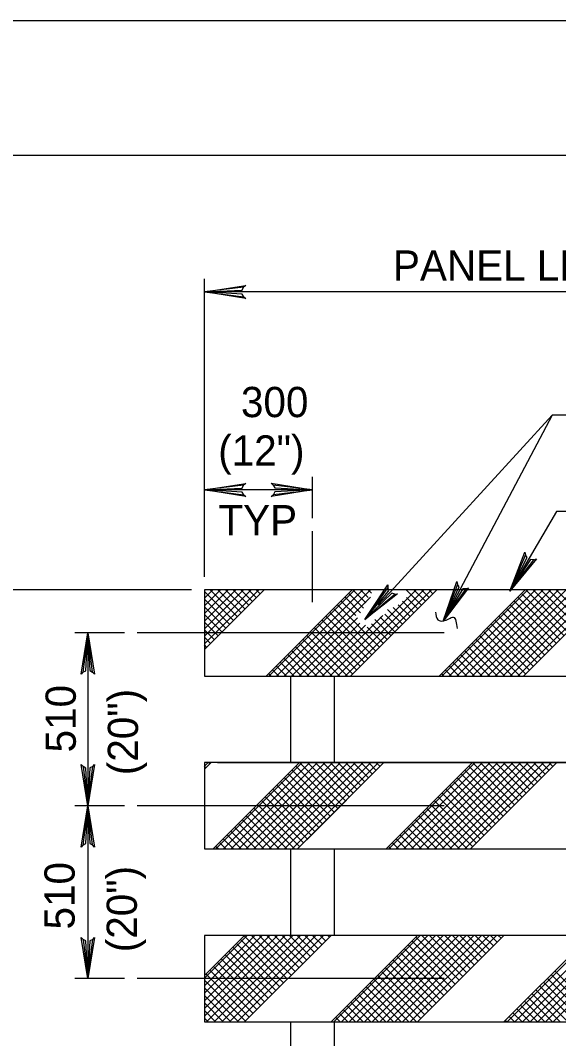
# Model space of a CAD drawing. Extents: x -4 to 901, y -468 to 720.
# Drawn here: x 119.8 to 179.6, y 606.9 to 720 of the extents above; entities that cross this region are included whole.
import ezdxf

# ---------------------------------------------------------------- set-up
doc = ezdxf.new("R2010")
doc.units = 0
for name, color, linetype in [('1', 7, 'Continuous'), ('2', 7, 'Continuous'), ('3', 7, 'Continuous'), ('PLT-BNDY', 7, 'Continuous')]:
    doc.layers.add(name, color=color, linetype=linetype)

msp = doc.modelspace()

# ---------------------------------------------------------------- linework, layer by layer
at = {"layer": '1'}
msp.add_lwpolyline([(822.258, 141.027875), (822.258, 705.027875), (36.258, 705.027875), (36.258, 141.027875), (822.258, 141.027875), (822.258, 167.386875), (622.258, 167.386875), (622.258, 232.064375), (822.258, 232.064375), (822.258, 261.027875), (622.258, 261.027875), (622.258, 141.027875), (701.0595, 141.027875), (701.0595, 167.386875), (701.0595, 141.027875), (778.0595, 141.027875), (778.0595, 167.386875), (778.0595, 155.070375), (822.258, 155.070375)], dxfattribs=at)
at = {"layer": '2'}
for p, q in [((140.2805, 658.235125), (140.2805, 691.305125)), ((284.2805, 689.865125), (140.2805, 689.865125)), ((152.2805, 664.733125), (152.2805, 669.313125)), ((152.2805, 667.873125), (140.2805, 667.873125)), ((152.2805, 655.413125), (152.2805, 663.293125)), ((138.8405, 656.795125), (93.0485, 656.795125)), ((140.2805, 650.161125), (146.9145, 656.795125)), ((147.14125, 647.205125), (156.74125, 656.805125)), ((156.5145, 647.195125), (166.1145, 656.795125)), ((166.34125, 647.205125), (175.94125, 656.805125)), ((175.7145, 647.195125), (185.3145, 656.795125)), ((131.3825, 651.995125), (125.8845, 651.995125)), ((127.3245, 651.995125), (127.3245, 632.795125)), ((166.9105, 651.995125), (132.8225, 651.995125)), ((140.2805, 636.847125), (141.0285, 637.595125)), ((141.25525, 628.005125), (150.85525, 637.605125)), ((141.7205, 637.595125), (192.7225, 637.595125)), ((150.6285, 627.995125), (160.2285, 637.595125)), ((160.45525, 628.005125), (170.05525, 637.605125)), ((169.8285, 627.995125), (179.4285, 637.595125)), ((151.6465, 629.013125), (156.0525, 633.419125)), ((131.3825, 632.795125), (125.8845, 632.795125)), ((127.3245, 632.795125), (127.3245, 613.595125)), ((166.9105, 632.795125), (132.8225, 632.795125)), ((140.2805, 613.933125), (144.7425, 618.395125)), ((144.7425, 608.795125), (154.3425, 618.395125)), ((154.3425, 608.795125), (163.9425, 618.395125)), ((163.9425, 608.795125), (173.5425, 618.395125)), ((173.5425, 608.795125), (183.1425, 618.395125)), ((131.3825, 613.595125), (125.8845, 613.595125)), ((166.9105, 613.595125), (132.8225, 613.595125))]:
    msp.add_line(p, q, dxfattribs=at)
for points in [[(144.6405, 689.317125), (144.4765, 689.633125), (140.2805, 689.865125), (144.6405, 689.317125), (144.8625, 689.127125), (140.2805, 689.865125), (144.4745, 690.073125), (144.6265, 690.385125), (140.2805, 689.865125), (144.8625, 690.593125), (144.6265, 690.385125)], [(178.9225, 676.169125), (160.9405, 656.573125)], [(183.7225, 676.169125), (178.9225, 676.169125), (166.9905, 653.625125)], [(144.6405, 667.327125), (144.4765, 667.643125), (140.2805, 667.873125), (144.6405, 667.327125), (144.8625, 667.135125), (140.2805, 667.873125), (144.4745, 668.081125), (144.6265, 668.393125), (140.2805, 667.873125), (144.8625, 668.603125), (144.6265, 668.393125)], [(147.9205, 668.421125), (148.0845, 668.105125), (152.2805, 667.873125), (147.9205, 668.421125), (147.6985, 668.613125), (152.2805, 667.873125), (148.0865, 667.667125), (147.9345, 667.355125), (152.2805, 667.873125), (147.6985, 667.145125), (147.9345, 667.355125)], [(184.1885, 665.477125), (179.3885, 665.477125), (174.1945, 656.647125)], [(176.8765, 660.127125), (176.5225, 660.147125), (174.1945, 656.647125), (176.8765, 660.127125), (177.1545, 660.223125), (174.1945, 656.647125), (176.1425, 660.367125), (175.9505, 660.657125), (174.1945, 656.647125), (175.8905, 660.965125), (175.9505, 660.657125)], [(160.2105, 656.669125), (160.6505, 657.333125), (160.6445, 657.019125)], [(169.3385, 656.893125), (168.9845, 656.897125), (166.8165, 653.297125), (169.3385, 656.893125), (169.6125, 657.001125), (166.8165, 653.297125), (168.5945, 657.099125), (168.3905, 657.381125), (166.8165, 653.297125), (168.3165, 657.687125), (168.3905, 657.381125)], [(140.2805, 655.856375), (141.21925, 656.795125)], [(140.2805, 655.007875), (142.06775, 656.795125)], [(140.2805, 654.159375), (142.91625, 656.795125)], [(140.2805, 653.310875), (143.76475, 656.795125)], [(140.2805, 652.462375), (144.61325, 656.795125)], [(140.2805, 651.613875), (145.46175, 656.795125)], [(140.2805, 650.765375), (146.31025, 656.795125)], [(143.49725, 653.377875), (140.2805, 656.594625)], [(143.9215, 653.802125), (140.9285, 656.795125)], [(144.34575, 654.226375), (141.777, 656.795125)], [(144.77, 654.650625), (142.6255, 656.795125)], [(145.19425, 655.074875), (143.474, 656.795125)], [(145.6185, 655.499125), (144.3225, 656.795125)], [(146.04275, 655.923375), (145.171, 656.795125)], [(146.467, 656.347625), (146.0195, 656.795125)], [(147.43525, 647.205125), (157.03525, 656.805125)], [(148.27375, 647.195125), (157.87375, 656.795125)], [(149.12225, 647.195125), (158.72225, 656.795125)], [(154.21325, 647.195125), (163.81325, 656.795125)], [(155.06225, 647.195125), (164.66225, 656.795125)], [(157.61375, 654.237625), (155.89725, 655.961125)], [(155.91075, 647.195125), (165.51075, 656.795125)], [(157.95825, 654.742375), (156.3215, 656.385375)], [(158.22325, 655.326375), (156.74575, 656.809625)], [(158.4725, 655.926625), (157.60725, 656.795125)], [(158.83275, 656.414875), (158.454, 656.795125)], [(159.5005, 655.597125), (159.8345, 656.101125)], [(159.9845, 656.101125), (159.5245, 655.461125)], [(159.8345, 656.101125), (160.2105, 656.669125)], [(160.3765, 656.647125), (159.9845, 656.101125)], [(160.1425, 655.939125), (160.6965, 656.605125)], [(160.9405, 656.573125), (160.1425, 655.705125)], [(161.4385, 656.307125), (161.0965, 656.401125), (160.1425, 655.471125)], [(160.1425, 655.207125), (161.4385, 656.307125), (161.7305, 656.341125), (160.1425, 655.089125)], [(160.6965, 656.605125), (160.7705, 656.695125), (160.6445, 657.019125), (160.3765, 656.647125)], [(164.39575, 655.081375), (162.6885, 656.795125)], [(164.82075, 655.504625), (163.53525, 656.795125)], [(165.246, 655.928125), (164.38225, 656.795125)], [(165.671, 656.351625), (165.22925, 656.795125)], [(166.09575, 656.776375), (166.06725, 656.805125)], [(166.63525, 647.205125), (176.23525, 656.805125)], [(167.47375, 647.195125), (177.07375, 656.795125)], [(168.32225, 647.195125), (177.92225, 656.795125)], [(169.17075, 647.195125), (178.77075, 656.795125)], [(170.01925, 647.195125), (179.61925, 656.795125)], [(170.86775, 647.195125), (180.46775, 656.795125)], [(171.71625, 647.195125), (181.31625, 656.795125)], [(172.56475, 647.195125), (182.16475, 656.795125)], [(173.41325, 647.195125), (183.01325, 656.795125)], [(174.26225, 647.195125), (183.86225, 656.795125)], [(179.77, 651.270375), (175.09725, 655.961125)], [(175.11075, 647.195125), (184.71075, 656.795125)], [(180.195, 651.693875), (175.5215, 656.385375)], [(180.62025, 652.117125), (175.94575, 656.809625)], [(181.04525, 652.540625), (176.80725, 656.795125)], [(181.47025, 652.964125), (177.654, 656.795125)], [(181.8955, 653.387625), (178.50125, 656.795125)], [(182.3205, 653.810875), (179.34775, 656.795125)], [(143.073, 652.953625), (140.2805, 655.746125)], [(142.6485, 652.529125), (140.2805, 654.897125)], [(149.97075, 647.195125), (158.7265, 655.950875)], [(159.71975, 650.423375), (155.04875, 655.112625)], [(157.09375, 653.909625), (155.473, 655.536875)], [(159.5245, 655.461125), (158.0885, 653.465125), (159.5005, 655.597125)], [(159.6525, 654.701125), (158.0885, 653.465125), (159.5605, 655.239125)], [(159.6105, 654.949125), (158.0885, 653.465125), (159.6385, 654.779125)], [(159.5605, 655.239125), (160.1425, 655.939125)], [(160.1425, 655.705125), (159.5865, 655.097125)], [(160.1425, 655.471125), (159.6105, 654.949125)], [(159.6385, 654.779125), (160.1425, 655.207125)], [(160.1425, 655.089125), (159.6525, 654.701125)], [(163.1205, 653.810875), (161.81625, 655.120125)], [(163.5455, 654.234375), (162.27225, 655.512625)], [(163.97075, 654.657875), (162.71225, 655.921125)], [(178.91975, 650.423375), (174.24875, 655.112625)], [(179.345, 650.846875), (174.673, 655.536875)], [(142.22425, 652.104875), (140.2805, 654.048625)], [(153.36475, 647.195125), (160.08825, 653.918625)], [(158.4445, 649.153125), (153.776, 653.839875)], [(158.86975, 649.576625), (154.20025, 654.264125)], [(159.29475, 649.999875), (154.6245, 654.688375)], [(161.42025, 652.117125), (159.8005, 653.743125)], [(161.84525, 652.540625), (160.32025, 654.071375)], [(162.27025, 652.964125), (160.633, 654.607625)], [(162.6955, 653.387625), (161.26425, 654.824375)], [(177.6445, 649.153125), (172.976, 653.839875)], [(178.06975, 649.576625), (173.40025, 654.264125)], [(178.49475, 649.999875), (173.8245, 654.688375)], [(141.8, 651.680625), (140.2805, 653.200125)], [(150.81925, 647.195125), (157.28325, 653.659125)], [(151.66775, 647.195125), (157.548, 653.075375)], [(152.51625, 647.195125), (158.1635, 652.842375)], [(157.5945, 648.306125), (152.9275, 652.991375)], [(158.0195, 648.729625), (153.35175, 653.415625)], [(160.145, 650.846875), (158.3525, 652.646375)], [(160.57, 651.270375), (158.85625, 652.990625)], [(160.995, 651.693875), (159.201, 653.494875)], [(176.7945, 648.306125), (172.1275, 652.991375)], [(177.2195, 648.729625), (172.55175, 653.415625)], [(126.7785, 647.635125), (127.0945, 647.797125), (127.3245, 651.995125), (126.7785, 647.635125), (126.5865, 647.411125), (127.3245, 651.995125), (127.5325, 647.801125), (127.8445, 647.647125), (127.3245, 651.995125), (128.0545, 647.411125), (127.8445, 647.647125)], [(141.37575, 651.256375), (140.2805, 652.351625)], [(140.9515, 650.832125), (140.2805, 651.503125)], [(156.1605, 647.195125), (151.654, 651.719375)], [(156.74425, 647.459375), (152.079, 652.142875)], [(157.16925, 647.882875), (152.50325, 652.567125)], [(175.3605, 647.195125), (170.8555, 651.719375)], [(175.94425, 647.459375), (171.279, 652.142875)], [(176.36925, 647.882875), (171.70325, 652.567125)], [(140.52725, 650.407875), (140.2805, 650.654625)], [(153.62, 647.195125), (150.37875, 650.449125)], [(154.467, 647.195125), (150.80375, 650.872625)], [(155.31375, 647.195125), (151.22875, 651.296125)], [(172.8195, 647.195125), (169.58, 650.447125)], [(173.6665, 647.195125), (170.00525, 650.870625)], [(174.5135, 647.195125), (170.43025, 651.294125)], [(151.07925, 647.195125), (149.10325, 649.178875)], [(151.92625, 647.195125), (149.5285, 649.602375)], [(152.773, 647.195125), (149.9535, 650.025625)], [(170.279, 647.195125), (168.30475, 649.176875)], [(171.126, 647.195125), (168.73, 649.600375)], [(171.97275, 647.195125), (169.155, 650.023875)], [(149.3855, 647.195125), (148.25325, 648.331875)], [(150.2325, 647.195125), (148.67825, 648.755375)], [(168.5855, 647.195125), (167.45475, 648.330125)], [(169.432, 647.195125), (167.87975, 648.753375)], [(147.69175, 647.195125), (147.403, 647.485125)], [(148.53875, 647.195125), (147.828, 647.908625)], [(149.8805, 637.595125), (149.8805, 647.195125), (154.6805, 647.195125), (154.6805, 637.595125)], [(166.8915, 647.195125), (166.6045, 647.483125)], [(167.73825, 647.195125), (167.0295, 647.906625)], [(127.8725, 637.153125), (127.5565, 636.991125), (127.3245, 632.795125), (127.8725, 637.153125), (128.0645, 637.377125), (127.3245, 632.795125), (127.1185, 636.987125), (126.8065, 637.141125), (127.3245, 632.795125), (126.5965, 637.377125), (126.8065, 637.141125)], [(140.2805, 637.184375), (140.69125, 637.595125)], [(140.44525, 637.011875), (140.2805, 637.177125)], [(140.8695, 637.436125), (140.71125, 637.595125)], [(141.54925, 628.005125), (151.14925, 637.605125)], [(141.54925, 628.005125), (151.14925, 637.605125)], [(142.38775, 627.995125), (151.98775, 637.595125)], [(143.23625, 627.995125), (152.83625, 637.595125)], [(144.08475, 627.995125), (153.68475, 637.595125)], [(144.93325, 627.995125), (154.53325, 637.595125)], [(145.78175, 627.995125), (155.38175, 637.595125)], [(146.63025, 627.995125), (156.23025, 637.595125)], [(147.47875, 627.995125), (157.07875, 637.595125)], [(148.32725, 627.995125), (157.92725, 637.595125)], [(149.17625, 627.995125), (158.77625, 637.595125)], [(154.684, 632.070125), (150.0095, 636.762625)], [(150.02475, 627.995125), (159.62475, 637.595125)], [(155.10925, 632.493625), (150.43475, 637.186125)], [(155.53425, 632.917125), (150.85975, 637.609625)], [(155.95925, 633.340625), (151.72125, 637.595125)], [(156.38425, 633.764125), (152.568, 637.595125)], [(156.8095, 634.187625), (153.41525, 637.595125)], [(157.2345, 634.610875), (154.26175, 637.595125)], [(157.6595, 635.034375), (155.10875, 637.595125)], [(158.08475, 635.457875), (155.95575, 637.595125)], [(158.50975, 635.881375), (156.8025, 637.595125)], [(158.93475, 636.304625), (157.64925, 637.595125)], [(159.36, 636.728125), (158.49625, 637.595125)], [(159.785, 637.151625), (159.33325, 637.605125)], [(160.74925, 628.005125), (170.34925, 637.605125)], [(160.74925, 628.005125), (170.34925, 637.605125)], [(161.58775, 627.995125), (171.18775, 637.595125)], [(162.43625, 627.995125), (172.03625, 637.595125)], [(163.28475, 627.995125), (172.88475, 637.595125)], [(164.13325, 627.995125), (173.73325, 637.595125)], [(164.98175, 627.995125), (174.58175, 637.595125)], [(165.83025, 627.995125), (175.43025, 637.595125)], [(166.67875, 627.995125), (176.27875, 637.595125)], [(167.52725, 627.995125), (177.12725, 637.595125)], [(168.37625, 627.995125), (177.97625, 637.595125)], [(173.884, 632.070125), (169.2095, 636.762625)], [(169.22475, 627.995125), (178.82475, 637.595125)], [(174.30925, 632.493625), (169.63475, 637.186125)], [(174.73425, 632.917125), (170.05975, 637.609625)], [(175.15925, 633.340625), (170.92125, 637.595125)], [(175.58425, 633.764125), (171.768, 637.595125)], [(176.0095, 634.187625), (172.61525, 637.595125)], [(176.4345, 634.610875), (173.46175, 637.595125)], [(176.8595, 635.034375), (174.30875, 637.595125)], [(177.28475, 635.457875), (175.15575, 637.595125)], [(177.70975, 635.881375), (176.0025, 637.595125)], [(178.13475, 636.304625), (176.84925, 637.595125)], [(178.56, 636.728125), (177.69625, 637.595125)], [(178.985, 637.151625), (178.53325, 637.605125)], [(153.834, 631.223375), (149.1595, 635.915875)], [(154.259, 631.646875), (149.5845, 636.339375)], [(173.034, 631.223375), (168.3595, 635.915875)], [(173.459, 631.646875), (168.7845, 636.339375)], [(152.55875, 629.952875), (147.88425, 634.645375)], [(152.98375, 630.376375), (148.30925, 635.068875)], [(153.40875, 630.799875), (148.73425, 635.492375)], [(171.75875, 629.952875), (167.08425, 634.645375)], [(172.18375, 630.376375), (167.50925, 635.068875)], [(172.60875, 630.799875), (167.93425, 635.492375)], [(151.2835, 628.682625), (146.617, 633.366875)], [(151.7085, 629.106125), (147.04125, 633.791125)], [(152.1335, 629.529625), (147.459, 634.222125)], [(170.4835, 628.682625), (165.809, 633.375125)], [(170.9085, 629.106125), (166.234, 633.798625)], [(171.3335, 629.529625), (166.659, 634.222125)], [(126.7785, 628.435125), (127.0945, 628.597125), (127.3245, 632.795125), (126.7785, 628.435125), (126.5865, 628.211125), (127.3245, 632.795125), (127.5325, 628.601125), (127.8445, 628.447125), (127.3245, 632.795125), (128.0545, 628.211125), (127.8445, 628.447125)], [(150.27425, 627.995125), (145.7685, 632.518375)], [(150.8585, 628.259125), (146.19275, 632.942625)], [(169.47425, 627.995125), (164.9685, 632.518375)], [(170.0585, 628.259125), (165.384, 632.951625)], [(147.73375, 627.995125), (144.49575, 631.245625)], [(148.58075, 627.995125), (144.92, 631.669875)], [(149.42775, 627.995125), (145.34425, 632.094125)], [(166.93375, 627.995125), (163.6835, 631.257875)], [(167.78075, 627.995125), (164.10875, 631.681375)], [(168.62775, 627.995125), (164.53375, 632.104875)], [(145.193, 627.995125), (143.223, 629.972875)], [(146.04025, 627.995125), (143.64725, 630.397125)], [(146.88675, 627.995125), (144.0715, 630.821375)], [(164.393, 627.995125), (162.423, 629.972875)], [(165.24025, 627.995125), (162.84725, 630.397125)], [(166.08675, 627.995125), (163.2715, 630.821375)], [(143.49925, 627.995125), (142.3745, 629.124375)], [(144.34625, 627.995125), (142.79875, 629.548625)], [(162.69925, 627.995125), (161.5745, 629.124375)], [(163.54625, 627.995125), (161.99875, 629.548625)], [(141.80575, 627.995125), (141.526, 628.275875)], [(142.652, 627.995125), (141.95, 628.699875)], [(149.8805, 618.395125), (149.8805, 627.995125)], [(154.6805, 627.995125), (154.6805, 618.395125)], [(161.0055, 627.995125), (160.726, 628.275875)], [(161.85225, 627.995125), (161.15, 628.699875)], [(127.8725, 617.953125), (127.5565, 617.791125), (127.3245, 613.595125), (127.8725, 617.953125), (128.0645, 618.177125), (127.3245, 613.595125), (127.1185, 617.787125), (126.8065, 617.941125), (127.3245, 613.595125), (126.5965, 618.177125), (126.8065, 617.941125)], [(140.2805, 613.662125), (145.0145, 618.395125)], [(140.2805, 612.813625), (145.863, 618.395125)], [(140.2805, 611.965375), (146.71175, 618.395125)], [(140.2805, 611.116625), (147.5605, 618.395125)], [(140.2805, 610.268125), (148.409, 618.395125)], [(140.2805, 609.420125), (149.2575, 618.395125)], [(140.504, 608.795125), (150.106, 618.395125)], [(141.35275, 608.795125), (150.955, 618.395125)], [(142.2015, 608.795125), (151.8035, 618.395125)], [(143.05, 608.795125), (152.652, 618.395125)], [(143.8985, 608.795125), (153.50075, 618.395125)], [(149.0745, 613.127125), (144.2745, 617.927125)], [(149.49875, 613.551375), (144.69875, 618.351375)], [(149.923, 613.975625), (145.5035, 618.395125)], [(150.34725, 614.399875), (146.352, 618.395125)], [(150.77175, 614.824375), (147.201, 618.395125)], [(151.196, 615.248625), (148.0495, 618.395125)], [(151.62025, 615.672875), (148.898, 618.395125)], [(152.0445, 616.097125), (149.7465, 618.395125)], [(152.46875, 616.521375), (150.595, 618.395125)], [(152.893, 616.945625), (151.4435, 618.395125)], [(153.31725, 617.369875), (152.292, 618.395125)], [(153.7415, 617.794125), (153.1405, 618.395125)], [(154.16575, 618.218375), (153.989, 618.395125)], [(154.6565, 608.795125), (164.2585, 618.395125)], [(155.505, 608.795125), (165.107, 618.395125)], [(156.35375, 608.795125), (165.95575, 618.395125)], [(157.2025, 608.795125), (166.8045, 618.395125)], [(158.051, 608.795125), (167.65325, 618.395125)], [(158.8995, 608.795125), (168.5015, 618.395125)], [(159.748, 608.795125), (169.35, 618.395125)], [(160.59675, 608.795125), (170.199, 618.395125)], [(161.4455, 608.795125), (171.0475, 618.395125)], [(162.294, 608.795125), (171.896, 618.395125)], [(163.14275, 608.795125), (172.7445, 618.395125)], [(168.13725, 612.988625), (163.33575, 617.788375)], [(168.5615, 613.412875), (163.76, 618.212625)], [(168.98575, 613.837125), (164.42625, 618.395125)], [(169.41, 614.261375), (165.27475, 618.395125)], [(169.83425, 614.685875), (166.12375, 618.395125)], [(170.25825, 615.110125), (166.97225, 618.395125)], [(170.6825, 615.534375), (167.82075, 618.395125)], [(171.10675, 615.958875), (168.66975, 618.395125)], [(171.531, 616.383125), (169.51825, 618.395125)], [(171.955, 616.807375), (170.36675, 618.395125)], [(172.37925, 617.231875), (171.2155, 618.395125)], [(172.8035, 617.656125), (172.06425, 618.395125)], [(173.22775, 618.080375), (172.913, 618.395125)], [(173.91625, 608.795125), (183.51825, 618.395125)], [(174.76475, 608.795125), (184.36675, 618.395125)], [(175.6135, 608.795125), (185.2155, 618.395125)], [(176.46225, 608.795125), (186.06425, 618.395125)], [(177.31075, 608.795125), (186.913, 618.395125)], [(178.15925, 608.795125), (187.76125, 618.395125)], [(179.00775, 608.795125), (188.60975, 618.395125)], [(147.80175, 611.854375), (143.00175, 616.654375)], [(148.226, 612.278625), (143.426, 617.078625)], [(148.65025, 612.702875), (143.85025, 617.502875)], [(166.86475, 611.715625), (162.06325, 616.515375)], [(167.289, 612.139875), (162.4875, 616.939625)], [(167.71325, 612.564125), (162.91175, 617.363875)], [(146.529, 610.581625), (141.729, 615.381625)], [(146.95325, 611.005875), (142.15325, 615.805875)], [(147.3775, 611.430125), (142.5775, 616.230125)], [(166.0165, 610.866875), (161.215, 615.666625)], [(166.4405, 611.291125), (161.639, 616.090875)], [(145.6805, 609.733125), (140.8805, 614.533125)], [(146.10475, 610.157375), (141.30475, 614.957375)], [(164.74375, 609.593875), (159.94225, 614.393625)], [(165.168, 610.018125), (160.3665, 614.817875)], [(165.59225, 610.442375), (160.79075, 615.242125)], [(184.026, 609.672625), (179.2225, 614.472375)], [(144.83175, 608.884375), (140.2805, 613.435625)], [(145.256, 609.308625), (140.456, 614.108625)], [(162.99675, 608.795125), (158.66975, 613.120625)], [(163.8455, 608.795125), (159.094, 613.544875)], [(164.31975, 609.169375), (159.51825, 613.969125)], [(182.3575, 608.795125), (177.95025, 613.198875)], [(183.178, 608.823625), (178.3745, 613.623375)], [(183.602, 609.248125), (178.7985, 614.047875)], [(144.0725, 608.795125), (140.2805, 612.587125)], [(161.2995, 608.795125), (157.8215, 612.271875)], [(162.148, 608.795125), (158.2455, 612.696125)], [(179.811, 608.795125), (176.678, 611.925625)], [(180.65975, 608.795125), (177.102, 612.350125)], [(181.50875, 608.795125), (177.52625, 612.774625)], [(143.224, 608.795125), (140.2805, 611.738625)], [(142.3755, 608.795125), (140.2805, 610.890125)], [(158.75325, 608.795125), (156.54875, 610.998875)], [(159.602, 608.795125), (156.973, 611.423125)], [(160.45075, 608.795125), (157.39725, 611.847625)], [(178.11325, 608.795125), (175.82975, 611.076875)], [(178.962, 608.795125), (176.254, 611.501125)], [(141.527, 608.795125), (140.2805, 610.041625)], [(156.20725, 608.795125), (155.27625, 609.725875)], [(157.056, 608.795125), (155.7005, 610.150125)], [(157.90475, 608.795125), (156.12475, 610.574375)], [(175.56675, 608.795125), (174.5575, 609.803625)], [(176.4155, 608.795125), (174.98175, 610.227875)], [(177.2645, 608.795125), (175.40575, 610.652375)], [(140.6785, 608.795125), (140.2805, 609.193125)], [(149.8805, 584.369125), (149.8805, 608.795125)], [(154.6805, 608.795125), (154.6805, 585.299125)], [(155.3585, 608.795125), (154.852, 609.301375)], [(173.86875, 608.795125), (173.70925, 608.954625)], [(174.718, 608.795125), (174.1335, 609.379125)]]:
    msp.add_lwpolyline(points, dxfattribs=at)
for points in [[(140.2805, 656.795125), (140.2805, 647.195125), (284.2805, 647.195125), (284.2805, 656.795125)], [(140.2805, 637.595125), (140.2805, 627.995125), (271.9685, 627.995125), (271.9685, 637.595125)], [(140.2805, 618.395125), (140.2805, 608.795125), (271.9685, 608.795125), (271.9685, 618.395125)]]:
    msp.add_lwpolyline(points, close=True, dxfattribs=at)
msp.add_spline([(165.9445, 654.309125), (166.2265, 653.459125), (166.7925, 653.317125), (167.9265, 653.741125), (168.3505, 652.467125)], degree=3, dxfattribs=at)
at = {"layer": 'PLT-BNDY'}
msp.add_lwpolyline([(-3.742, 720.027875), (837.258, 720.027875), (837.258, 126.027875), (-3.742, 126.027875)], close=True, dxfattribs=at)

# ---------------------------------------------------------------- texts
at = {"layer": '3'}
for s, height, p in [('PANEL LENGTH VARIES WITH REQUIRED', 3.359988, (161.2265, 691.117125)), ('300', 3.36, (144.337, 675.958125)), ('(12")', 3.36, (141.811, 670.574625)), ('TYP', 3.36, (141.836, 662.833125))]:
    msp.add_text(s, height=height, dxfattribs=at).set_placement(p)
for s, p in [('510', (125.98925, 638.716625)), ('(20")', (132.90525, 636.190625)), ('510', (125.86175, 619.051625)), ('(20")', (132.77775, 616.525625))]:
    msp.add_text(s, height=3.36, rotation=90, dxfattribs=at).set_placement(p)

doc.saveas('drawing.dxf')
